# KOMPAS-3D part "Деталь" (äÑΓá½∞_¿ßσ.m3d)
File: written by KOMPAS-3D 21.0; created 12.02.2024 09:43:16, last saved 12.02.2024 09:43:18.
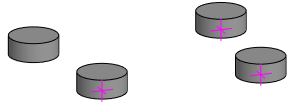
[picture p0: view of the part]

Document properties: Автор: alg; Полное имя файла: C:\Деталь_исх.m3d

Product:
- Part/product: Деталь

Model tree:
1. Эскиз:1
2. Элемент выдавливания:1
     Расстояние 1 = 10
3. Эскиз:2
4. Массив по точкам:1
5. Экземпляр ( 1 )
6. Тело 1
7. Экземпляр ( 2 )  (with: Тело 1)
8. Экземпляр ( 3 )  (with: Тело 1)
